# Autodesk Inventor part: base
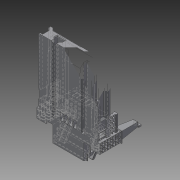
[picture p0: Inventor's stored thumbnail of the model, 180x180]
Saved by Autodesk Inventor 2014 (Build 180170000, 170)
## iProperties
Created: 2013-07
Part Number: base
Material: Generic
Document SubType Name: Modeling
Designer: Brent J. Rosenburgh
Density: 1 g/cm^3
Appearance: Default
Author: Brent J. Rosenburgh
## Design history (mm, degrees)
sketch "Sketch1"
  geometry: L1 (-56, -78)-(56, -78); L2 (56, -78)-(56, -100); L3 (56, -100)-(-56, -100); L4 (-56, -100)-(-56, -78); 1 further point
  constraints: 8 end point, 2 parallel, 1 horizontal, 1 perpendicular
extrude "Extrusion1" new body sketch "Sketch1" distance "d0" = 136; taper "d1" = 0 deg
sketch "Sketch2"
  geometry: L1 (0, 136)-(12, 136); L2 (12, 136)-(12, 124); L3 (12, 124)-(0, 124); L4 (0, 124)-(0, 136); L5 (112, 136)-(100, 136); L6 (100, 136)-(100, 124); L7 (100, 124)-(112, 124); L8 (112, 124)-(112, 136); 1 further point
  constraints: 16 end point, 4 parallel, 2 horizontal, 2 perpendicular
extrude "Extrusion2" join sketch "Sketch2" distance "d2" = 16; taper "d3" = 0 deg
sketch "Sketch3"
  geometry: L1 (0, 136)-(0, 124) reference; L2 (0, 124)-(12, 124) reference; L3 (12, 124)-(12, 136) reference; L4 (12, 136)-(0, 136) reference; L5 (15, 121)-(-3, 121); L6 (-3, 121)-(-3, 139); L7 (-3, 139)-(15, 139); L8 (15, 139)-(15, 121); 1 further point
  constraints: 8 end point, 2 parallel, 1 horizontal, 1 perpendicular
extrude "Extrusion3" join sketch "Sketch3" distance "d4" = 38; taper "d5" = 0 deg
sketch "Sketch4"
  geometry: L1 (112, 136)-(100, 136) reference; L2 (100, 136)-(100, 124) reference; L3 (100, 124)-(112, 124) reference; L4 (112, 124)-(112, 136) reference; L5 (115, 121)-(97, 121); L6 (97, 121)-(97, 139); L7 (97, 139)-(115, 139); L8 (115, 139)-(115, 121); 1 further point
  constraints: 8 end point, 2 parallel, 1 horizontal, 1 perpendicular
extrude "Extrusion4" join sketch "Sketch4" distance "d6" = 38; taper "d7" = 0 deg
sketch "Sketch5"
  geometry: L1 (15, 121)-(-3, 121) reference; L2 (15, 139)-(15, 121) reference; L3 (-3, 139)-(15, 139) reference; L4 (-3, 121)-(-3, 139) reference; 1 further point
extrude "Extrusion5" join sketch "Sketch5" distance "d8" = 1; taper "d9" = 45 deg
sketch "Sketch6"
  geometry: L1 (-4, 120)-(-4, 140) reference; L2 (16, 120)-(-4, 120) reference; L3 (16, 140)-(16, 120) reference; L4 (-4, 140)-(16, 140) reference; 1 further point
extrude "Extrusion6" join sketch "Sketch6" distance "d10" = 1; taper "d11" = 0 deg
sketch "Sketch7"
  geometry: L1 (-4, 140)-(-4, 120) reference; L2 (-4, 120)-(16, 120) reference; L3 (16, 120)-(16, 140) reference; L4 (16, 140)-(-4, 140) reference; 1 further point
extrude "Extrusion7" join sketch "Sketch7" distance "d12" = 1; taper "d13" = -45 deg
sketch "Sketch8"
  geometry: L1 (115, 121)-(97, 121) reference; L2 (115, 139)-(115, 121) reference; L3 (97, 139)-(115, 139) reference; L4 (97, 121)-(97, 139) reference; 1 further point
extrude "Extrusion8" join sketch "Sketch8" distance "d14" = 1; taper "d15" = 45 deg
sketch "Sketch9"
  geometry: L1 (96, 120)-(96, 140) reference; L2 (116, 120)-(96, 120) reference; L3 (116, 140)-(116, 120) reference; L4 (96, 140)-(116, 140) reference; 1 further point
extrude "Extrusion9" join sketch "Sketch9" distance "d16" = 1; taper "d17" = 0 deg
sketch "Sketch10"
  geometry: L1 (96, 140)-(96, 120) reference; L2 (96, 120)-(116, 120) reference; L3 (116, 120)-(116, 140) reference; L4 (116, 140)-(96, 140) reference; 1 further point
extrude "Extrusion10" join sketch "Sketch10" distance "d18" = 1; taper "d19" = -45 deg
sketch "Sketch11"
  geometry: L1 (113, 137)-(99, 137); L2 (99, 137)-(99, 123); L3 (99, 123)-(113, 123); L4 (113, 123)-(113, 137); L5 (113, 137)-(99, 123); L6 (99, 137)-(113, 123); 2 further points
  constraints: 12 end point, 2 midpoint, 2 parallel, 1 horizontal, 1 perpendicular
extrude "Extrusion11" join sketch "Sketch11" distance "d20" = 34; taper "d21" = -5 deg
sketch "Sketch12"
  geometry: L1 (-1, 123)-(13, 123); L2 (13, 123)-(13, 137); L3 (13, 137)-(-1, 137); L4 (-1, 137)-(-1, 123); L5 (-1, 123)-(13, 137); L6 (13, 123)-(-1, 137); 2 further points
  constraints: 12 end point, 2 midpoint, 2 parallel, 1 horizontal, 1 perpendicular
extrude "Extrusion12" join sketch "Sketch12" distance "d22" = 34; taper "d23" = -5 deg
sketch "Sketch13"
  geometry: L1 (110.025, 134.025)-(110.025, 125.975) reference; L2 (101.975, 134.025)-(110.025, 134.025) reference; L3 (101.975, 125.975)-(101.975, 134.025) reference; L4 (110.025, 125.975)-(101.975, 125.975) reference; 1 further point
extrude "Extrusion13" join sketch "Sketch13" distance "d24" = 1; taper "d25" = 45 deg
sketch "Sketch14"
  geometry: L1 (1.975, 125.975)-(1.975, 134.025) reference; L2 (10.025, 125.975)-(1.975, 125.975) reference; L3 (10.025, 134.025)-(10.025, 125.975) reference; L4 (1.975, 134.025)-(10.025, 134.025) reference; 1 further point
extrude "Extrusion14" join sketch "Sketch14" distance "d26" = 1; taper "d27" = 45 deg
sketch "Sketch15"
  geometry: L1 (111.025, 124.975)-(100.975, 124.975) reference; L2 (111.025, 135.025)-(111.025, 124.975) reference; L3 (100.975, 135.025)-(111.025, 135.025) reference; L4 (100.975, 124.975)-(100.975, 135.025) reference; 1 further point
extrude "Extrusion15" join sketch "Sketch15" distance "d28" = 4.5; taper "d29" = 0 deg
sketch "Sketch16"
  geometry: L1 (0.975, 135.025)-(11.025, 135.025) reference; L2 (0.975, 124.975)-(0.975, 135.025) reference; L3 (11.025, 124.975)-(0.975, 124.975) reference; L4 (11.025, 135.025)-(11.025, 124.975) reference; 1 further point
extrude "Extrusion16" join sketch "Sketch16" distance "d30" = 4.5; taper "d31" = 0 deg
sketch "Sketch17"
  geometry: L1 (-10.051, 4.5)-(0, 4.5) reference; L2 (-10.051, 0)-(-10.051, 4.5) reference; L3 (-2.826, 4.5)-(-2.826, -0.41); L4 (-2.826, -0.41)-(-6.702, -0.41); L5 (-6.702, -0.41)-(-10.051, -1.07); L6 (-10.051, -1.07)-(-10.051, 0); 1 further point
  constraints: 8 end point, 2 parallel, 1 perpendicular, 1 point on line
extrude "Extrusion17" cut sketch "Sketch17" distance "d32" = 115.75; taper "d33" = 0 deg
sketch "Sketch18"
  geometry: L1 (0, 14)-(5.994, 14); L2 (5.994, 14)-(5.994, 10); L3 (5.994, 10)-(0, 10); L4 (0, 10)-(0, 14); 1 further point
  constraints: 8 end point, 2 parallel, 1 horizontal, 1 perpendicular
extrude "Extrusion18" join sketch "Sketch18" distance "d34" = 29.25; taper "d35" = 0 deg
sketch "Sketch19"
  geometry: L1 (14.949, 13.961)-(8.949, 13.961); L2 (8.949, 13.961)-(8.949, 9.961); L3 (8.949, 9.961)-(14.949, 9.961); L4 (14.949, 9.961)-(14.949, 13.961); 1 further point
  constraints: 8 end point, 2 parallel, 1 horizontal, 1 perpendicular
extrude "Extrusion19" join sketch "Sketch19" distance "d36" = 29.25; taper "d37" = 0 deg
sketch "Sketch20"
  geometry: L1 (0, 29.25)-(6, 29.25) reference; L2 (5, 3)-(1, 3); L3 (1, 3)-(1, 8); L4 (1, 8)-(5, 8); L5 (5, 8)-(5, 3); L6 (5, 11)-(1, 11); L7 (1, 11)-(1, 16); L8 (1, 16)-(5, 16); L9 (5, 16)-(5, 11); L10 (5, 19)-(1, 19); L11 (1, 19)-(1, 24); L12 (1, 24)-(5, 24); L13 (5, 24)-(5, 19); L14 (1, 27)-(5, 27); L15 (5, 27)-(5, 29.25); L16 (5, 29.25)-(1, 29.25); L17 (1, 29.25)-(1, 27); 1 further point
  constraints: 32 end point, 8 parallel, 4 horizontal, 4 perpendicular, 2 point on line
extrude "Extrusion20" join sketch "Sketch20" distance "d38" = 10.25; taper "d39" = 0 deg
sketch "Sketch21"
  geometry: L1 (0, 29.25)-(5.994, 29.25) reference; L2 (5, 3)-(1, 3); L3 (1, 3)-(1, 8); L4 (1, 8)-(5, 8); L5 (5, 8)-(5, 3); L6 (1, 11)-(5, 11); L7 (5, 11)-(5, 16); L8 (5, 16)-(1, 16); L9 (1, 16)-(1, 11); L10 (5, 19)-(1, 19); L11 (1, 19)-(1, 24); L12 (1, 24)-(5, 24); L13 (5, 24)-(5, 19); L14 (1, 27)-(5, 27); L15 (5, 27)-(5, 29.25); L16 (5, 29.25)-(1, 29.25); L17 (1, 29.25)-(1, 27); 1 further point
  constraints: 32 end point, 8 parallel, 4 horizontal, 4 perpendicular, 1 point on line
extrude "Extrusion21" join sketch "Sketch21" distance "d40" = 10.25; taper "d41" = 0 deg
sketch "Sketch22"
  geometry: L1 (5, 5)-(1, 5); L2 (1, 5)-(1, 6); L3 (1, 6)-(5, 6); L4 (5, 6)-(5, 5); 1 further point
  constraints: 8 end point, 2 parallel, 1 horizontal, 1 perpendicular
extrude "Extrusion22" join sketch "Sketch22" distance "d42" = 28; taper "d43" = 0 deg
sketch "Sketch23"
  geometry: L1 (4, 0)-(4, -9.961) reference; L2 (0, 0)-(0, -9.961) reference; L3 (4, -4.981)-(0, -4.981); L4 (0, -4.981)-(0, -4); L5 (0, -4)-(4, -4); L6 (4, -4)-(4, -4.981); 1 further point
  constraints: 8 end point, 2 parallel, 1 horizontal, 1 midpoint, 1 perpendicular, 1 point on line
extrude "Extrusion23" join sketch "Sketch23" distance "d44" = 28; taper "d45" = 0 deg
sketch "Sketch24"
  geometry: L1 (-13, 36)-(0, 36); L2 (0, 36)-(0, 32); L3 (0, 32)-(-13, 32); L4 (-13, 32)-(-13, 36); 1 further point
  constraints: 8 end point, 2 parallel, 1 horizontal, 1 perpendicular
extrude "Extrusion24" join sketch "Sketch24" distance "d46" = 19; taper "d47" = 0 deg
sketch "Sketch25"
  geometry: L1 (13, 36)-(0, 36); L2 (0, 36)-(0, 32); L3 (0, 32)-(13, 32); L4 (13, 32)-(13, 36); 1 further point
  constraints: 8 end point, 2 parallel, 1 horizontal, 1 perpendicular
extrude "Extrusion25" join sketch "Sketch25" distance "d48" = 19; taper "d49" = 0 deg
sketch "Sketch26"
  geometry: L1 (0, 36)-(0, 32) reference; L2 (13, 32)-(13, 36) reference; L3 (0, 36)-(-32, 17); L4 (0, 32)-(-32, 13); L5 (-32, 13)-(-32, 17); 1 further point
  constraints: 6 end point, 2 parallel
extrude "Extrusion26" join sketch "Sketch26" distance "d50" = 9; taper "d51" = 0 deg
sketch "Sketch27"
  geometry: L1 (0, 32)-(0, 36) reference; L2 (0, 36)-(32, 17); L3 (32, 17)-(32, 13); L4 (32, 13)-(0, 32); 1 further point
  constraints: 6 end point, 2 parallel
extrude "Extrusion27" join sketch "Sketch27" distance "d52" = 9; taper "d53" = 0 deg
sketch "Sketch28"
  geometry: L1 (-41, -100)-(41, -100) reference; L2 (29, -100)-(-29, -100); L3 (-29, -100)-(-29, -94.5); L4 (-29, -94.5)-(29, -94.5); L5 (29, -94.5)-(29, -100); 1 further point
  constraints: 8 end point, 2 parallel, 1 horizontal, 1 perpendicular, 1 point on line
  dimensions: "d54" = 5.5 distance of L2.end L3.end
extrude "Extrusion28" join sketch "Sketch28" distance "d55" = 28; taper "d56" = 0 deg
sketch "Sketch29"
  geometry: L1 (29, -94.5)-(-29, -94.5); L2 (-29, -94.5)-(-29, -89); L3 (-29, -89)-(29, -89); L4 (29, -89)-(29, -94.5); 1 further point
  constraints: 8 end point, 2 parallel, 1 horizontal, 1 perpendicular
extrude "Extrusion29" join sketch "Sketch29" distance "d57" = 19; taper "d58" = 0 deg
sketch "Sketch30"
  geometry: L1 (29, -89)-(-29, -89); L2 (-29, -89)-(-29, -83.5); L3 (-29, -83.5)-(29, -83.5); L4 (29, -83.5)-(29, -89); 1 further point
  constraints: 8 end point, 2 parallel, 1 horizontal, 1 perpendicular
  dimensions: "d59" = 5.5 distance of L1.end L2.end
extrude "Extrusion30" join sketch "Sketch30" distance "d60" = 10; taper "d61" = 0 deg
sketch "Sketch32"
  geometry: L1 (-17, 11)-(-12, 11); L2 (-12, 11)-(-12, 2); L3 (-12, 2)-(-17, 2); L4 (-17, 2)-(-17, 11); L5 (-7, 11)-(-2, 11); L6 (-2, 11)-(-2, 2); L7 (-2, 2)-(-7, 2); L8 (-7, 2)-(-7, 11); 1 further point
  constraints: 16 end point, 4 parallel, 2 horizontal, 2 perpendicular
extrude "Extrusion32" join sketch "Sketch32" distance "d64" = 10.75; taper "d65" = 0 deg
sketch "Sketch33"
  geometry: L1 (17, 11)-(12, 11); L2 (12, 11)-(12, 2); L3 (12, 2)-(17, 2); L4 (17, 2)-(17, 11); L5 (2, 11)-(7, 11); L6 (7, 11)-(7, 2); L7 (7, 2)-(2, 2); L8 (2, 2)-(2, 11); 1 further point
  constraints: 16 end point, 4 parallel, 2 horizontal, 2 perpendicular
extrude "Extrusion33" join sketch "Sketch33" distance "d66" = 10.75; taper "d67" = 0 deg
sketch "Sketch34"
  geometry: L1 (58, 0)-(58, 10) reference; L2 (58, 8)-(53, 8); L3 (53, 8)-(53, 2); L4 (53, 2)-(58, 2); L5 (58, 2)-(58, 8); 1 further point
  constraints: 8 end point, 2 parallel, 1 horizontal, 1 perpendicular, 1 point on line
extrude "Extrusion34" join sketch "Sketch34" distance "d68" = 14.5; taper "d69" = 0 deg
sketch "Sketch35"
  geometry: L1 (0, 0)-(0, 10) reference; L2 (0, 8)-(5, 8); L3 (5, 8)-(5, 2); L4 (5, 2)-(0, 2); L5 (0, 2)-(0, 8); 1 further point
  constraints: 8 end point, 2 parallel, 1 horizontal, 1 perpendicular, 1 point on line
extrude "Extrusion35" join sketch "Sketch35" distance "d70" = 14.5; taper "d71" = 0 deg
sketch "Sketch36"
  geometry: L1 (58, -9)-(58, 0) reference; L2 (0, -9)-(0, 0) reference; L3 (0, -7)-(5, -7); L4 (5, -7)-(5, -2); L5 (5, -2)-(0, -2); L6 (0, -2)-(0, -7); L7 (58, -2)-(53, -2); L8 (53, -2)-(53, -7); L9 (53, -7)-(58, -7); L10 (58, -7)-(58, -2); 1 further point
  constraints: 16 end point, 4 parallel, 2 horizontal, 2 perpendicular, 2 point on line
extrude "Extrusion36" join sketch "Sketch36" distance "d72" = 14.5; taper "d73" = 0 deg
sketch "Sketch37"
  geometry: L1 (58, -9)-(58, 0) reference; L2 (0, -9)-(0, 0) reference; L3 (0, -7)-(5, -7); L4 (5, -7)-(5, -2); L5 (5, -2)-(0, -2); L6 (0, -2)-(0, -7); L7 (58, -2)-(53, -2); L8 (53, -2)-(53, -7); L9 (53, -7)-(58, -7); L10 (58, -7)-(58, -2); 1 further point
  constraints: 16 end point, 4 parallel, 2 horizontal, 2 perpendicular, 2 point on line
extrude "Extrusion37" join sketch "Sketch37" distance "d74" = 14.5; taper "d75" = 0 deg
sketch "Sketch38"
  geometry: L1 (-28, 0)-(-28, 16.5) reference; L2 (-18, 16.5)-(-28, 16.5); L3 (-28, 16.5)-(-28, 15); L4 (-28, 15)-(-18, 15); L5 (-18, 15)-(-18, 16.5); L6 (-9, 11)-(-19, 11); L7 (-19, 11)-(-19, 9.5); L8 (-19, 9.5)-(-9, 9.5); L9 (-9, 9.5)-(-9, 11); L10 (0, 5.5)-(-10, 5.5); L11 (-10, 5.5)-(-10, 4); L12 (-10, 4)-(0, 4); L13 (0, 4)-(0, 5.5); 1 further point
  constraints: 24 end point, 6 parallel, 3 horizontal, 3 perpendicular, 1 point on line
  dimensions: "d76" = 1.5 distance of L7.end L6.end
extrude "Extrusion38" join sketch "Sketch38" distance "d77" = 2; taper "d78" = 0 deg
sketch "Sketch39"
  geometry: L1 (18, 16.5)-(28, 16.5); L2 (28, 16.5)-(28, 15); L3 (28, 15)-(18, 15); L4 (18, 15)-(18, 16.5); L5 (9, 11)-(19, 11); L6 (19, 11)-(19, 9.5); L7 (19, 9.5)-(9, 9.5); L8 (9, 9.5)-(9, 11); L9 (0, 5.5)-(10, 5.5); L10 (10, 5.5)-(10, 4); L11 (10, 4)-(0, 4); L12 (0, 4)-(0, 5.5); 1 further point
  constraints: 24 end point, 6 parallel, 3 horizontal, 3 perpendicular
  dimensions: "d79" = 1.5 distance of L5.end L6.end
extrude "Extrusion39" join sketch "Sketch39" distance "d80" = 2; taper "d81" = 0 deg
sketch "Sketch40"
  geometry: L1 (31, -83.5)-(-31, -83.5); L2 (-31, -83.5)-(-31, -85); L3 (-31, -85)-(31, -85); L4 (31, -85)-(31, -83.5); 1 further point
  constraints: 8 end point, 2 parallel, 1 horizontal, 1 perpendicular
extrude "Extrusion40" join sketch "Sketch40" distance "d82" = 1; taper "d83" = 0 deg
sketch "Sketch41"
  geometry: L1 (29, -94.5)-(29, -90.5) reference; L2 (29, -90.5)-(31, -90.5) reference; L3 (31, -89)-(31, -90.5) reference; L4 (-31, -89)-(31, -89) reference; L5 (-31, -90.5)-(-31, -89) reference; L6 (-29, -90.5)-(-31, -90.5) reference; L7 (-29, -90.5)-(29, -90.5); 1 further point
  constraints: 2 end point, 1 perpendicular
extrude "Extrusion41" join sketch "Sketch41" distance "d84" = 1; taper "d85" = 0 deg
sketch "Sketch42"
  geometry: L1 (29, -96)-(31, -96) reference; L2 (31, -94.5)-(31, -96) reference; L3 (-31, -94.5)-(31, -94.5) reference; L4 (-31, -96)-(-31, -94.5) reference; L5 (-29, -96)-(-31, -96) reference; L6 (-29, -100)-(29, -100) reference; L7 (-29, -96)-(29, -96); 1 further point
  constraints: 2 end point, 1 parallel
extrude "Extrusion42" join sketch "Sketch42" distance "d86" = 1; taper "d87" = 0 deg
sketch "Sketch43"
  geometry: L1 (41, -78)-(-41, -78) reference; L2 (-31, -78)-(31, -78); L3 (31, -78)-(31, -79.5); L4 (31, -79.5)-(-31, -79.5); L5 (-31, -79.5)-(-31, -78); 1 further point
  constraints: 8 end point, 2 parallel, 1 horizontal, 1 perpendicular, 1 point on line
  dimensions: "d88" = 1.5 distance of L2.end L3.end
extrude "Extrusion43" join sketch "Sketch43" distance "d89" = 1; taper "d90" = 0 deg
sketch "Sketch44"
  geometry: L1 (-56, -100)-(-56, -78) reference; L2 (56, -78)-(56, -100) reference; L3 (-56, -97)-(-51, -97); L4 (-51, -97)-(-51, -86); L5 (-51, -86)-(-56, -81); L6 (56, -97)-(51, -97); L7 (51, -97)-(51, -86); L8 (51, -86)-(56, -81); 1 further point
  constraints: 12 end point, 4 perpendicular, 4 point on line, 1 parallel
extrude "Extrusion44" cut sketch "Sketch44" distance "d91" = 91.5; taper "d92" = 0 deg
sketch "Sketch45"
  geometry: L1 (56, -100)-(-56, -100) reference; L2 (-56, -81)-(-51, -86) reference; L3 (-51, -86)-(-51, -97) reference; L4 (-29, -100)-(-29, -97); L5 (-29, -97)-(-34.5, -91.5); L6 (-34.5, -91.5)-(-34.5, -86); L7 (-25, -100)-(-25, -97); L8 (-25, -97)-(-19.5, -91.5); L9 (-19.5, -91.5)-(-19.5, -86); L10 (-19.5, -86)-(-34.5, -86); L11 (29, -100)-(29, -97); L12 (29, -97)-(34.5, -91.5); L13 (34.5, -91.5)-(34.5, -86); L14 (25, -100)-(25, -97); L15 (25, -97)-(19.5, -91.5); L16 (19.5, -91.5)-(19.5, -86); L17 (19.5, -86)-(34.5, -86); 1 further point
  constraints: 28 end point, 9 parallel, 5 perpendicular, 4 point on line
extrude "Extrusion45" cut sketch "Sketch45" distance "d93" = 120.5; taper "d94" = 0 deg
sketch "Sketch46"
  geometry: L1 (34.288, 91.75)-(77.796, 91.75); L2 (77.796, 91.75)-(77.796, 88); L3 (77.796, 88)-(34.288, 88); L4 (34.288, 88)-(34.288, 91.75); 1 further point
  constraints: 8 end point, 2 parallel, 1 horizontal, 1 perpendicular
extrude "Extrusion46" join sketch "Sketch46" distance "d95" = 14; taper "d96" = 0 deg
sketch "Sketch47"
  geometry: L1 (43.507, 0)-(43.507, 14) reference; L2 (0, 14)-(43.507, 14); L3 (43.507, 14)-(43.507, 10); L4 (43.507, 10)-(0, 10); L5 (0, 10)-(0, 14); 1 further point
  constraints: 8 end point, 2 parallel, 1 horizontal, 1 perpendicular, 1 point on line
extrude "Extrusion47" join sketch "Sketch47" distance "d97" = 1; taper "d98" = 0 deg
sketch "Sketch48"
  geometry: L1 (6.48, 10)-(7, 10); L2 (7, 10)-(7, 0); L3 (7, 0)-(6.48, 0); L4 (6.48, 0)-(6.48, 10); L5 (36.48, 10)-(37, 10); L6 (37, 10)-(37, 0); L7 (37, 0)-(36.48, 0); L8 (36.48, 0)-(36.48, 10); L9 (29, 10)-(29.52, 10); L10 (29.52, 10)-(29.52, 0); L11 (29.52, 0)-(29, 0); L12 (29, 0)-(29, 10); L13 (13.834, 10)-(14.354, 10); L14 (14.354, 10)-(14.354, 0); L15 (14.354, 0)-(13.834, 0); L16 (13.834, 0)-(13.834, 10); L17 (21.234, 10)-(21.754, 10); L18 (21.754, 10)-(21.754, 0); L19 (21.754, 0)-(21.234, 0); L20 (21.234, 0)-(21.234, 10); 1 further point
  constraints: 40 end point, 10 parallel, 5 horizontal, 5 perpendicular
extrude "Extrusion48" cut sketch "Sketch48" distance "d99" = 0.5; taper "d100" = 0 deg
sketch "Sketch49"
  geometry: L1 (-56, -78)-(56, -78) reference; L2 (-19.5, -86)-(-19.5, -91.5) reference; L3 (-19.5, -91.5)-(-25, -97) reference; L4 (-51, -78)-(-46, -83); L5 (51, -78)-(46, -83); L6 (46, -83)-(-46, -83); 1 further point
  constraints: 6 end point, 3 perpendicular, 2 point on line
extrude "Extrusion49" cut sketch "Sketch49" distance "d101" = 4.25; taper "d102" = 0 deg
sketch "Sketch50"
  geometry: L1 (77.796, -33)-(34.288, -33) reference; L2 (41.316, -110)-(70.796, -110); L3 (70.796, -110)-(70.796, -33); L4 (70.796, -33)-(41.316, -33); L5 (41.316, -33)-(41.316, -110); L6 (95, -33)-(106.949, -33); L7 (106.949, -33)-(106.949, -110); L8 (106.949, -110)-(95, -110); L9 (95, -110)-(95, -33); L10 (17, -110)-(5, -110); L11 (5, -110)-(5, -33); L12 (5, -33)-(17, -33); L13 (17, -33)-(17, -110); 1 further point
  constraints: 24 end point, 6 parallel, 3 horizontal, 3 perpendicular, 3 point on line
extrude "Extrusion50" cut sketch "Sketch50" distance "d103" = 5; taper "d104" = 0 deg
sketch "Sketch51"
  geometry: L1 (41.316, -33)-(70.796, -33) reference; L2 (41.316, -110)-(41.316, -33) reference; L3 (70.796, -110)-(41.316, -110) reference; L4 (70.796, -33)-(70.796, -110) reference; 1 further point
extrude "Extrusion51" cut sketch "Sketch51" distance "d105" = 13.25; taper "d106" = 0 deg
sketch "Sketch52"
  geometry: L1 (17, -110)-(5, -110) reference; L2 (17, -33)-(17, -110) reference; L3 (5, -33)-(17, -33) reference; L4 (11, -33)-(11, -110); 1 further point
  constraints: 2 end point, 2 midpoint
extrude "Extrusion52" cut sketch "Sketch52" distance "d107" = 13.25; taper "d108" = 0 deg
sketch "Sketch53"
  geometry: L1 (95, -33)-(106.949, -33) reference; L2 (95, -110)-(95, -33) reference; L3 (106.949, -110)-(95, -110) reference; L4 (100.975, -33)-(100.975, -110); 1 further point
  constraints: 2 end point, 2 midpoint
extrude "Extrusion53" cut sketch "Sketch53" distance "d109" = 13.25; taper "d110" = 0 deg
chamfer "Chamfer1" distance "d111" = 5.97; stored, may be unused: second distance "d112" = 2, angle "d113" = 45 deg
sketch "Sketch54"
  geometry: L1 (70.796, -33)-(70.796, -110) reference; L2 (41.316, -110)-(41.316, -33) reference; L3 (41.316, -33)-(34.288, -33) reference; L4 (77.796, -33)-(70.796, -33) reference; L5 (95, -110)-(95, -33) reference; L6 (17, -33)-(17, -110) reference; L7 (5, -33)-(17, -33) reference; L8 (17, -33)-(34.288, -33); L9 (77.796, -33)-(95, -33); L10 (17, -110)-(41.316, -110); L11 (70.796, -110)-(95, -110); 1 further point
  constraints: 8 end point, 3 collinear, 1 parallel
extrude "Extrusion54" cut sketch "Sketch54" distance "d114" = 5; taper "d115" = 0 deg
sketch "Sketch55"
  geometry: L1 (95, -33)-(100.975, -33) reference; L2 (95, -33)-(95, -5); L3 (95, -5)-(114, -5); L4 (114, -5)-(114, -14); L5 (114, -14)-(100.975, -14); L6 (100.975, -14)-(100.975, -33); 1 further point
  constraints: 10 end point, 3 perpendicular, 2 parallel
sketch "Sketch56"
  geometry: L1 (41.316, -33)-(70.796, -33) reference; L2 (70.796, -33)-(70.796, -110) reference; L3 (70.796, -33)-(70.796, -14); L4 (41.316, -33)-(41.316, -14); L5 (70.796, -110)-(41.316, -110) reference; L6 (41.316, -14)-(41.316, -0.595); L7 (41.316, -0.595)-(70.796, -0.595); L8 (70.796, -0.595)-(70.796, -14); 1 further point
  constraints: 10 end point, 2 perpendicular, 1 collinear, 1 parallel
sketch "Sketch57"
  geometry: L1 (11, -33)-(17, -33) reference; L2 (17, -110)-(11, -110) reference; L3 (17, -33)-(17, -5); L4 (17, -5)-(-3, -5); L5 (-3, -5)-(-3, -14); L6 (-3, -14)-(11, -14); L7 (11, -14)-(11, -33); 1 further point
  constraints: 10 end point, 3 parallel, 2 perpendicular
extrude "Extrusion55" cut sketch "Sketch57" distance "d116" = 10.25; taper "d117" = 0 deg
extrude "Extrusion56" cut sketch "Sketch55" distance "d118" = 10.25; taper "d119" = 0 deg
extrude "Extrusion57" cut sketch "Sketch56" distance "d120" = 10.25; taper "d121" = 0 deg
sketch "Sketch58"
  geometry: L1 (70.796, -0.595)-(70.796, -110) reference; L2 (41.316, -0.595)-(70.796, -0.595) reference; L3 (41.316, -0.595)-(70.796, -0.595); L4 (70.796, -0.595)-(70.796, -14); L5 (70.796, -14)-(41.316, -14); L6 (41.316, -14)-(41.316, -0.595); 1 further point
  constraints: 8 end point, 2 parallel, 1 horizontal, 1 perpendicular, 1 point on line
extrude "Extrusion58" cut sketch "Sketch58" distance "d122" = 5.5; taper "d123" = 0 deg
fillet "Fillet1" dims "d124" = 12.25
fillet "Fillet2" dims "d125" = 8
chamfer "Chamfer2" distance "d126" = 13.22; stored, may be unused: second distance "d127" = 2, angle "d128" = 45 deg
chamfer "Chamfer3" distance "d129" = 2.22; stored, may be unused: second distance "d130" = 2, angle "d131" = 45 deg
chamfer "Chamfer4" distance "d132" = 93.72; stored, may be unused: second distance "d133" = 4, angle "d134" = 45 deg
chamfer "Chamfer5" distance "d135" = 95.97; stored, may be unused: second distance "d136" = 4, angle "d137" = 45 deg
chamfer "Chamfer6" distance "d138" = 95.97; stored, may be unused: second distance "d139" = 4, angle "d140" = 45 deg
sketch "Sketch59"
  geometry: L1 (70.796, 13.815)-(41.316, 13.815) reference; L2 (41.316, 33)-(70.796, 33) reference; L3 (55, 33)-(57, 33); L4 (57, 33)-(57, 13.815); L5 (57, 13.815)-(55, 13.815); L6 (55, 13.815)-(55, 33); L7 (63, 13.815)-(65, 13.815); L8 (65, 13.815)-(65, 33); L9 (65, 33)-(63, 33); L10 (63, 33)-(63, 13.815); L11 (49, 33)-(47, 33); L12 (47, 33)-(47, 13.815); L13 (47, 13.815)-(49, 13.815); L14 (49, 13.815)-(49, 33); 1 further point
  constraints: 24 end point, 6 parallel, 4 point on line, 3 horizontal, 3 perpendicular
extrude "Extrusion59" join sketch "Sketch59" distance "d141" = 14; taper "d142" = 0 deg
sketch "Sketch60"
  geometry: L1 (73.796, 18.595)-(44.316, 18.595) reference; L2 (50, 31.815)-(52, 31.815); L3 (52, 31.815)-(52, 18.595); L4 (52, 18.595)-(50, 18.595); L5 (50, 18.595)-(50, 31.815); L6 (58, 31.815)-(60, 31.815); L7 (60, 31.815)-(60, 18.595); L8 (60, 18.595)-(58, 18.595); L9 (58, 18.595)-(58, 31.815); L10 (66, 31.815)-(68, 31.815); L11 (68, 31.815)-(68, 18.595); L12 (68, 18.595)-(66, 18.595); L13 (66, 18.595)-(66, 31.815); 1 further point
  constraints: 24 end point, 6 parallel, 3 horizontal, 3 perpendicular, 3 point on line
extrude "Extrusion60" join sketch "Sketch60" distance "d143" = 14.75; taper "d144" = 0 deg
chamfer "Chamfer7" distance "d145" = 2.47; stored, may be unused: second distance "d146" = 4, angle "d147" = 45 deg
chamfer "Chamfer8" distance "d148" = 3; stored, may be unused: second distance "d149" = 4, angle "d150" = 45 deg
sketch "Sketch61"
  geometry: L1 (13, 36)-(0, 36) reference; L2 (0, 36)-(-32, 17) reference; L3 (-32, 17)-(-32, 13) reference; L4 (-32, 13)-(0, 32) reference; L5 (13, 32)-(13, 36) reference; L6 (-32, 14)-(0, 33); L7 (0, 33)-(13, 33); 1 further point
  constraints: 4 end point, 2 point on line, 1 parallel, 1 perpendicular
extrude "Extrusion61" join sketch "Sketch61" distance "d151" = 0.5; taper "d152" = 0 deg
sketch "Sketch62"
  geometry: L1 (0, 36)-(-13, 36) reference; L2 (-13, 36)-(-13, 32) reference; L3 (32, 13)-(32, 17) reference; L4 (32, 17)-(0, 36) reference; L5 (32, 14)-(0, 33); L6 (0, 33)-(-13, 33); 1 further point
  constraints: 4 end point, 2 point on line, 1 parallel, 1 perpendicular
extrude "Extrusion62" join sketch "Sketch62" distance "d153" = 0.5; taper "d154" = 0 deg
sketch "Sketch63"
  geometry: L1 (32, 17)-(0, 36) reference; L2 (0, 32)-(0, 36) reference; L3 (0, 32)-(32, 13) reference; L4 (32, 13)-(32, 17) reference; L5 (32, 14)-(0, 33); 1 further point
  constraints: 2 end point, 2 point on line, 1 parallel
extrude "Extrusion63" join sketch "Sketch63" distance "d155" = 0.5; taper "d156" = 0 deg
sketch "Sketch64"
  geometry: L1 (0, 36)-(0, 32) reference; L2 (0, 36)-(-32, 17) reference; L3 (-32, 17)-(-32, 13) reference; L4 (-32, 13)-(0, 32) reference; L5 (-32, 14)-(0, 33); 1 further point
  constraints: 2 end point, 2 point on line, 1 parallel
extrude "Extrusion64" join sketch "Sketch64" distance "d157" = 0.5; taper "d158" = 0 deg
sketch "Sketch65"
  geometry: L1 (-9.5, 4)-(-9.5, 1) reference; L2 (0, 4)-(0, 0) reference; L3 (0, 4)-(-9.5, 4) reference; L4 (-9.5, 1)-(0, 1); 1 further point
  constraints: 2 end point, 1 parallel, 1 point on line
extrude "Extrusion65" join sketch "Sketch65" distance "d159" = 0.5; taper "d160" = 0 deg
sketch "Sketch66"
  geometry: L1 (9.5, 1)-(9.5, 4) reference; L2 (0, 4)-(9.5, 4) reference; L3 (0, 0)-(0, 4) reference; L4 (10, 1)-(9.5, 1) reference; L5 (9.5, 1)-(0, 1); 1 further point
  constraints: 2 end point, 1 collinear, 1 point on line
extrude "Extrusion66" join sketch "Sketch66" distance "d161" = 0.5; taper "d162" = 0 deg
sketch "Sketch67"
  geometry: L1 (0, 0)-(0, 1) reference; L2 (9, 0)-(0, 0) reference; L3 (9, 1)-(9, 0) reference; L4 (9.5, 4)-(9.5, 1) reference; L5 (0, 1)-(9, 1); 1 further point
  constraints: 2 end point, 1 perpendicular
extrude "Extrusion67" cut sketch "Sketch67" distance "d163" = 0.5; taper "d164" = 0 deg
sketch "Sketch68"
  geometry: L1 (0, 0)-(0, 1) reference; L2 (0, 0)-(9, 0) reference; L3 (9, 1)-(9, 0) reference; L4 (0, 1)-(-0.5, 1) reference; L5 (0, 1)-(9, 1); 1 further point
  constraints: 2 end point, 1 collinear
extrude "Extrusion68" cut sketch "Sketch68" distance "d165" = 0.5; taper "d166" = 0 deg
sketch "Sketch69"
  geometry: L1 (-41, -78)-(-41, -100) reference; L2 (-41, -100)-(-29, -100) reference; L3 (-29, -100)-(-29, -85) reference; L4 (-29, -85)-(-31, -85) reference; L5 (31, -85)-(29, -85) reference; L6 (29, -85)-(29, -100) reference; L7 (29, -100)-(41, -100) reference; L8 (41, -100)-(41, -78) reference; L9 (41, -78)-(31, -78) reference; L10 (-31, -85)-(-41, -85); L11 (31, -85)-(41, -85); 1 further point
  constraints: 4 end point, 2 equal length, 2 point on line
extrude "Extrusion69" cut sketch "Sketch69" distance "d167" = 2; taper "d168" = 0 deg
sketch "Sketch70"
  geometry: L1 (29.5, 3)-(29.5, 19) reference; L2 (0, 22)-(0, 0) reference; L3 (121, 0)-(0, 0) reference; L4 (121, 0)-(121, 3) reference; L5 (0, 15)-(29.5, 15); L6 (29.5, 3)-(29.5, 0); L7 (4, 15)-(4, 0); L8 (15, 15)-(15, 0); 1 further point
  constraints: 8 end point, 7 point on line, 4 perpendicular
extrude "Extrusion70" cut sketch "Sketch70" distance "d169" = 2; taper "d170" = 0 deg
sketch "Sketch71"
  geometry: L1 (-29.5, 19)-(-29.5, 3) reference; L2 (-121, 0)-(0, 0) reference; L3 (0, 0)-(0, 22) reference; L4 (-121, 22)-(-121, 19) reference; L5 (0, 15)-(-29.5, 15); L6 (-29.5, 3)-(-29.5, 0); L7 (-15, 15)-(-15, 0); L8 (-4, 15)-(-4, 0); 1 further point
  constraints: 8 end point, 7 point on line, 4 perpendicular
extrude "Extrusion71" cut sketch "Sketch71" distance "d171" = 2; taper "d172" = 0 deg
sketch "Sketch72"
  geometry: L1 (0, 4)-(0, 0) reference; L2 (0, 4)-(-29.25, 4) reference; L3 (-29.25, 0)-(-29.25, 4) reference; L4 (0, 1)-(-29.25, 1); 1 further point
  constraints: 2 end point, 2 point on line, 1 perpendicular
extrude "Extrusion72" join sketch "Sketch72" distance "d173" = 0.5; taper "d174" = 0 deg
sketch "Sketch73"
  geometry: L1 (0, 0)-(0, 4) reference; L2 (29.25, 4)-(29.25, 0) reference; L3 (0, 4)-(29.25, 4) reference; L4 (29.25, 1)-(0, 1); 1 further point
  constraints: 2 end point, 2 point on line, 1 parallel
extrude "Extrusion73" join sketch "Sketch73" distance "d175" = 0.5; taper "d176" = 0 deg
chamfer "Chamfer9" distance "d177" = 3; stored, may be unused: second distance "d178" = 4, angle "d179" = 45 deg
chamfer "Chamfer10" distance "d180" = 1; stored, may be unused: second distance "d181" = 4, angle "d182" = 45 deg
chamfer "Chamfer11" distance "d183" = 1; stored, may be unused: second distance "d184" = 4, angle "d185" = 45 deg
chamfer "Chamfer12" distance "d186" = 1; stored, may be unused: second distance "d187" = 4, angle "d188" = 45 deg
chamfer "Chamfer13" distance "d189" = 2; stored, may be unused: second distance "d190" = 4, angle "d191" = 45 deg
chamfer "Chamfer14" distance "d192" = 0.5; stored, may be unused: second distance "d193" = 4, angle "d194" = 45 deg
chamfer "Chamfer15" distance "d195" = 14.25; stored, may be unused: second distance "d196" = 4, angle "d197" = 45 deg
chamfer "Chamfer16" distance "d198" = 3; stored, may be unused: second distance "d199" = 4, angle "d200" = 45 deg
sketch "Sketch74"
  geometry: L1 (0, 38)-(9, 38); L2 (9, 38)-(9, 34); L3 (9, 34)-(0, 34); L4 (0, 34)-(0, 38); L5 (10, 34)-(19, 34); L6 (19, 34)-(19, 38); L7 (19, 38)-(10, 38); L8 (10, 38)-(10, 34); L9 (-5.5, 33)-(3.5, 33); L10 (3.5, 33)-(3.5, 29); L11 (3.5, 29)-(-5.5, 29); L12 (-5.5, 29)-(-5.5, 33); L13 (4.5, 29)-(13.5, 29); L14 (13.5, 29)-(13.5, 33); L15 (13.5, 33)-(4.5, 33); L16 (4.5, 33)-(4.5, 29); L17 (0, 28)-(9, 28); L18 (9, 28)-(9, 24); L19 (9, 24)-(0, 24); L20 (0, 24)-(0, 28); L21 (10, 24)-(19, 24); L22 (19, 24)-(19, 28); L23 (19, 28)-(10, 28); L24 (10, 28)-(10, 24); L25 (14.5, 33)-(21, 33); L26 (21, 33)-(21, 29); L27 (21, 29)-(14.5, 29); L28 (14.5, 29)-(14.5, 33); L29 (4.5, 23)-(4.5, 19); L30 (3.5, 23)-(3.5, 19); L31 (10, 18)-(10, 14); L32 (9, 18)-(9, 14); L33 (0, 18)-(9, 18); L34 (9, 14)-(0, 14); L35 (-5.5, 23)-(3.5, 23); L36 (-5.5, 19)-(-5.5, 23); L37 (3.5, 19)-(-5.5, 19); L38 (0, 14)-(0, 18); L39 (13.5, 19)-(13.5, 23); L40 (4.5, 19)-(13.5, 19); L41 (13.5, 23)-(4.5, 23); L42 (19, 14)-(19, 18); L43 (19, 18)-(10, 18); L44 (14.5, 19)-(14.5, 23); L45 (21, 19)-(14.5, 19); L46 (10, 14)-(19, 14); L47 (14.5, 23)-(21, 23); L48 (21, 23)-(21, 19); L49 (4.5, 13)-(4.5, 9); L50 (3.5, 13)-(3.5, 9); L51 (10, 8)-(10, 4); L52 (9, 8)-(9, 4); L53 (0, 8)-(9, 8); L54 (9, 4)-(0, 4); L55 (-5.5, 13)-(3.5, 13); L56 (-5.5, 9)-(-5.5, 13); L57 (3.5, 9)-(-5.5, 9); L58 (0, 4)-(0, 8); L59 (13.5, 9)-(13.5, 13); L60 (4.5, 9)-(13.5, 9); L61 (13.5, 13)-(4.5, 13); L62 (19, 4)-(19, 8); L63 (19, 8)-(10, 8); L64 (14.5, 9)-(14.5, 13)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; 1 further point
  constraints: 184 end point, 46 parallel, 23 horizontal, 23 perpendicular
extrude "Extrusion74" cut sketch "Sketch74" distance "d201" = 0.5; taper "d202" = 0 deg
sketch "Sketch75"
  geometry: L1 (-5.5, -1)-(-5.5, 3); L2 (0, -6)-(0, -2); L3 (3.5, 3)-(3.5, -1); L4 (14.5, 3)-(21, 3); L5 (13.5, -1)-(13.5, 3); L6 (14.5, -1)-(14.5, 3); L7 (21, 3)-(21, -1); L8 (19, -2)-(10, -2); L9 (10, -2)-(10, -6); L10 (10, -6)-(19, -6); L11 (-8, -9)-(26, -9); L12 (9, 4)-(0, 4); L13 (10, 4)-(19, 4); L14 (19, 8)-(10, 8); L15 (19, 4)-(19, 8); L16 (-8, 38)-(-8, -9); L17 (26, -9)-(26, 38); L18 (9, 34)-(0, 34); L19 (10, 34)-(19, 34); L20 (19, 34)-(19, 38); L21 (19, 38)-(10, 38); L22 (10, 38)-(10, 34); L23 (0, 38)-(9, 38); L24 (9, 38)-(9, 34); L25 (0, 34)-(0, 38); L26 (0, 8)-(9, 8); L27 (3.5, 29)-(-5.5, 29); L28 (4.5, 29)-(13.5, 29); L29 (-5.5, 33)-(3.5, 33); L30 (-5.5, 29)-(-5.5, 33); L31 (3.5, 33)-(3.5, 29); L32 (13.5, 29)-(13.5, 33); L33 (13.5, 33)-(4.5, 33); L34 (3.5, 13)-(3.5, 9); L35 (9, 14)-(0, 14); L36 (9, 24)-(0, 24); L37 (0, 28)-(9, 28); L38 (9, 28)-(9, 24); L39 (0, 24)-(0, 28); L40 (4.5, 33)-(4.5, 29); L41 (4.5, 3)-(4.5, -1); L42 (-5.5, 3)-(3.5, 3); L43 (0, 4)-(0, 8); L44 (0, -2)-(9, -2); L45 (9, -2)-(9, -6); L46 (3.5, -1)-(-5.5, -1); L47 (9, -6)-(0, -6); L48 (4.5, -1)-(13.5, -1); L49 (3.5, 9)-(-5.5, 9); L50 (-5.5, 9)-(-5.5, 13); L51 (-5.5, 13)-(3.5, 13); L52 (19, -6)-(19, -2); L53 (4.5, 13)-(4.5, 9); L54 (10, 8)-(10, 4); L55 (9, 8)-(9, 4); L56 (4.5, 9)-(13.5, 9); L57 (13.5, 13)-(4.5, 13); L58 (13.5, 3)-(4.5, 3); L59 (13.5, 9)-(13.5, 13); L60 (21, -1)-(14.5, -1); L61 (0, 14)-(0, 18); L62 (3.5, 19)-(-5.5, 19); L63 (-5.5, 23)-(3.5, 23); L64 (-5.5, 19)-(-5.5, 23)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; 1 further point
  constraints: 184 end point, 46 parallel, 23 horizontal, 23 perpendicular
extrude "Extrusion75" cut sketch "Sketch75" distance "d203" = 0.5; taper "d204" = 0 deg
sketch "Sketch76"
  geometry: L1 (18, 38)-(9, 38); L2 (9, 38)-(9, 34); L3 (9, 34)-(18, 34); L4 (18, 34)-(18, 38); L5 (8, 34)-(-1, 34); L6 (-1, 34)-(-1, 38); L7 (-1, 38)-(8, 38); L8 (8, 38)-(8, 34); L9 (13, 33)-(4, 33); L10 (4, 33)-(4, 29); L11 (4, 29)-(13, 29); L12 (13, 29)-(13, 33); L13 (3, 29)-(-6, 29); L14 (-6, 29)-(-6, 33); L15 (-6, 33)-(3, 33); L16 (3, 33)-(3, 29); L17 (14, 33)-(14, 29); L18 (23, 33)-(14, 33); L19 (14, 29)-(23, 29); L20 (23, 29)-(23, 33); L21 (13, 23)-(4, 23); L22 (4, 19)-(13, 19); L23 (8, 28)-(8, 24); L24 (4, 23)-(4, 19); L25 (3, 23)-(3, 19); L26 (-1, 28)-(8, 28); L27 (8, 24)-(-1, 24); L28 (-1, 24)-(-1, 28); L29 (-6, 23)-(3, 23); L30 (3, 19)-(-6, 19); L31 (-6, 19)-(-6, 23); L32 (14, 23)-(14, 19); L33 (23, 23)-(14, 23); L34 (9, 28)-(9, 24); L35 (13, 19)-(13, 23); L36 (18, 28)-(9, 28); L37 (18, 24)-(18, 28); L38 (14, 19)-(23, 19); L39 (23, 19)-(23, 23); L40 (9, 24)-(18, 24); L41 (13, 13)-(4, 13); L42 (4, 9)-(13, 9); L43 (8, 18)-(8, 14); L44 (4, 13)-(4, 9); L45 (3, 13)-(3, 9); L46 (-1, 18)-(8, 18); L47 (8, 14)-(-1, 14); L48 (-1, 14)-(-1, 18); L49 (-6, 13)-(3, 13); L50 (3, 9)-(-6, 9); L51 (-6, 9)-(-6, 13); L52 (14, 13)-(14, 9); L53 (23, 13)-(14, 13); L54 (9, 18)-(9, 14); L55 (13, 9)-(13, 13); L56 (18, 18)-(9, 18); L57 (18, 14)-(18, 18); L58 (14, 9)-(23, 9); L59 (23, 9)-(23, 13); L60 (9, 14)-(18, 14); L61 (13, 3)-(4, 3); L62 (4, -1)-(13, -1); L63 (8, 8)-(8, 4); L64 (4, 3)-(4, -1)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; 1 further point
  constraints: 168 end point, 42 parallel, 21 horizontal, 21 perpendicular
extrude "Extrusion76" cut sketch "Sketch76" distance "d205" = 0.5; taper "d206" = 0 deg
sketch "Sketch77"
  geometry: L1 (9, 34)-(18, 34); L2 (9, 38)-(9, 34); L3 (8, 38)-(8, 34); L4 (18, 38)-(9, 38); L5 (18, 34)-(18, 38); L6 (13, 29)-(13, 33); L7 (13, 33)-(4, 33); L8 (-1, 34)-(-1, 38); L9 (-1, 38)-(8, 38); L10 (8, 34)-(-1, 34); L11 (4, 33)-(4, 29); L12 (4, 29)-(13, 29); L13 (8, 28)-(8, 24); L14 (3, 33)-(3, 29); L15 (13, 23)-(4, 23); L16 (4, 19)-(13, 19); L17 (4, 23)-(4, 19); L18 (3, 29)-(-6, 29); L19 (-6, 29)-(-6, 33); L20 (-6, 33)-(3, 33); L21 (-1, 28)-(8, 28); L22 (-1, 24)-(-1, 28); L23 (3, 23)-(3, 19); L24 (8, 24)-(-1, 24); L25 (8, 18)-(8, 14); L26 (-1, 18)-(8, 18); L27 (8, 14)-(-1, 14); L28 (-6, 23)-(3, 23); L29 (-6, 19)-(-6, 23); L30 (-1, 14)-(-1, 18); L31 (3, 19)-(-6, 19); L32 (-6, 13)-(3, 13); L33 (26.523, 38)-(-8, 38); L34 (-8, 38)-(-8, -3); L35 (-8, -3)-(26.523, -3); L36 (26.523, -3)-(26.523, 38); L37 (14, 33)-(14, 29); L38 (23, 33)-(14, 33); L39 (14, 29)-(23, 29); L40 (23, 29)-(23, 33); L41 (14, 23)-(14, 19); L42 (14, 19)-(23, 19); L43 (13, 19)-(13, 23); L44 (23, 19)-(23, 23); L45 (9, 24)-(18, 24); L46 (9, 28)-(9, 24); L47 (18, 28)-(9, 28); L48 (18, 24)-(18, 28); L49 (23, 23)-(14, 23); L50 (4, 13)-(4, 9); L51 (3, 13)-(3, 9); L52 (-6, 9)-(-6, 13); L53 (3, 9)-(-6, 9); L54 (-1, 4)-(-1, 8); L55 (-6, 3)-(3, 3); L56 (3, -1)-(-6, -1); L57 (-6, -1)-(-6, 3); L58 (8, 8)-(8, 4); L59 (8, 4)-(-1, 4); L60 (-1, 8)-(8, 8); L61 (18, 18)-(9, 18); L62 (9, 14)-(18, 14); L63 (9, 18)-(9, 14); L64 (18, 14)-(18, 18)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; 1 further point
  constraints: 168 end point, 42 parallel, 21 horizontal, 21 perpendicular
extrude "Extrusion77" cut sketch "Sketch77" distance "d207" = 0.5; taper "d208" = 0 deg
chamfer "Chamfer17" distance "d209" = 0.5; stored, may be unused: second distance "d210" = 4, angle "d211" = 45 deg
chamfer "Chamfer18" distance "d212" = 0.9; stored, may be unused: second distance "d213" = 4, angle "d214" = 45 deg
chamfer "Chamfer19" distance "d215" = 0.4; stored, may be unused: second distance "d216" = 4, angle "d217" = 45 deg
chamfer "Chamfer20" distance "d218" = 5.65; stored, may be unused: second distance "d219" = 4, angle "d220" = 45 deg
chamfer "Chamfer21" distance "d221" = 2; stored, may be unused: second distance "d222" = 4, angle "d223" = 45 deg
chamfer "Chamfer22" distance "d224" = 2; stored, may be unused: second distance "d225" = 4, angle "d226" = 45 deg
chamfer "Chamfer23" distance "d227" = 1; stored, may be unused: second distance "d228" = 4, angle "d229" = 45 deg
chamfer "Chamfer24" distance "d230" = 2; stored, may be unused: second distance "d231" = 4, angle "d232" = 45 deg
chamfer "Chamfer25" distance "d233" = 1; stored, may be unused: second distance "d234" = 4, angle "d235" = 45 deg
chamfer "Chamfer26" distance "d236" = 1; stored, may be unused: second distance "d237" = 4, angle "d238" = 45 deg
chamfer "Chamfer27" distance "d239" = 0.51; stored, may be unused: second distance "d240" = 4, angle "d241" = 45 deg
chamfer "Chamfer28" distance "d242" = 0.5; stored, may be unused: second distance "d243" = 4, angle "d244" = 45 deg
chamfer "Chamfer29" distance "d245" = 0.5; stored, may be unused: second distance "d246" = 4, angle "d247" = 45 deg
chamfer "Chamfer30" distance "d248" = 1; stored, may be unused: second distance "d249" = 4, angle "d250" = 45 deg
chamfer "Chamfer31" distance "d251" = 0.5; stored, may be unused: second distance "d252" = 4, angle "d253" = 45 deg
sketch "Sketch78"
  geometry: L1 (9.288, -39.5)-(52.796, -39.5); L2 (52.796, -39.5)-(52.796, -19.5); L3 (52.796, -19.5)-(9.288, -19.5); L4 (9.288, -19.5)-(9.288, -39.5); 1 further point
  constraints: 8 end point, 2 parallel, 1 horizontal, 1 perpendicular
extrude "Extrusion78" join sketch "Sketch78" distance "d254" = 0.5; taper "d255" = 0 deg
chamfer "Chamfer32" distance "d256" = 0.5; stored, may be unused: second distance "d257" = 4, angle "d258" = 45 deg
body "Solid1"
